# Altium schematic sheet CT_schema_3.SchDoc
size 300 x 163 mm
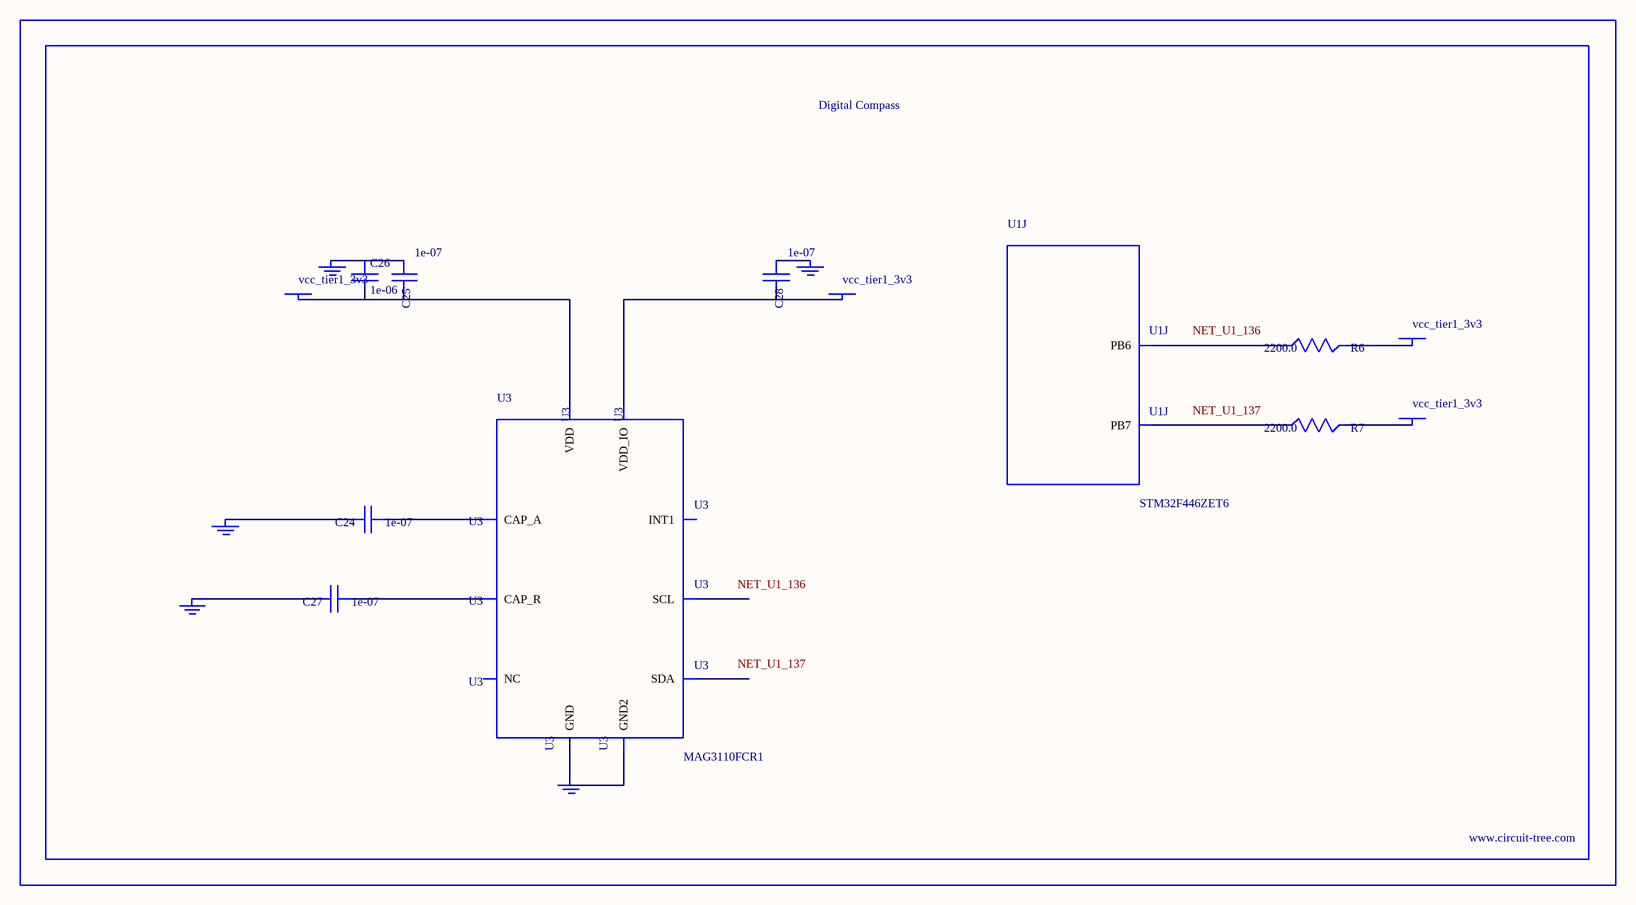
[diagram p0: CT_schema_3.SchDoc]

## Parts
BORDER2  (no value)
C24  1e-07  [C0402]
C25  1e-07  [C0402]
C26  1e-06  [C0603]
C27  1e-07  [C0402]
C28  1e-07  [C0402]
GND_INSTANCE_2_0  (no value)
GND_INSTANCE_2_1  (no value)
GND_INSTANCE_2_2  (no value)
GND_INSTANCE_2_3  (no value)
GND_INSTANCE_2_4  (no value)
POWER_INSTANCE_2_0  vcc_tier1_3v3
POWER_INSTANCE_2_1  vcc_tier1_3v3
POWER_INSTANCE_2_2  vcc_tier1_3v3
POWER_INSTANCE_2_3  vcc_tier1_3v3
R6  2200.0  [R0603]
R7  2200.0  [R0603]
U1  STM32F446ZET6  [LQFP144]  (part J of 11)
U3  MAG3110FCR1  [DFN-10]

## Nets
NetC24_1: C24.1 U3.1(CAP_A)
NetC24_2: C24.2 GND_INSTANCE_2_0.0(GND)
NetC25_1: C25.1 C26.1 GND_INSTANCE_2_1.0(GND)
NetC25_2: C25.2 C26.2 POWER_INSTANCE_2_0.0(PWR) U3.2(VDD)
NetC27_1: C27.1 U3.4(CAP_R)
NetC27_2: C27.2 GND_INSTANCE_2_2.0(GND)
NetC28_1: C28.1 GND_INSTANCE_2_3.0(GND)
NetC28_2: C28.2 POWER_INSTANCE_2_1.0(PWR) U3.8(VDD_IO)
NetGND_INSTANCE_2_4_0: GND_INSTANCE_2_4.0(GND) U3.5(GND) U3.10(GND2)
NetPOWER_INSTANCE_2_2_0: POWER_INSTANCE_2_2.0(PWR) R6.2
NetPOWER_INSTANCE_2_3_0: POWER_INSTANCE_2_3.0(PWR) R7.2
NetR6_1: R6.1 U1.136(PB6)
NetR7_1: R7.1 U1.137(PB7)

Not connected (* = marked no-connect by the designer): U3 3(NC) 6(SDA) 7(SCL) 9(INT1)

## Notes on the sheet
- Labels drawn without touching a wire or pin: NET_U1_136, NET_U1_137

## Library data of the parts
BORDER2 = BORDER_PAGE2
C24 C25 C27 C28 = C0402C104K3RACTU
C26 = C0603C105K3RACTU
GND_INSTANCE_2_0-GND_INSTANCE_2_4 = GND
POWER_INSTANCE_2_0-POWER_INSTANCE_2_3 = PWR
R6 R7 = RC0603JR-072K2L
